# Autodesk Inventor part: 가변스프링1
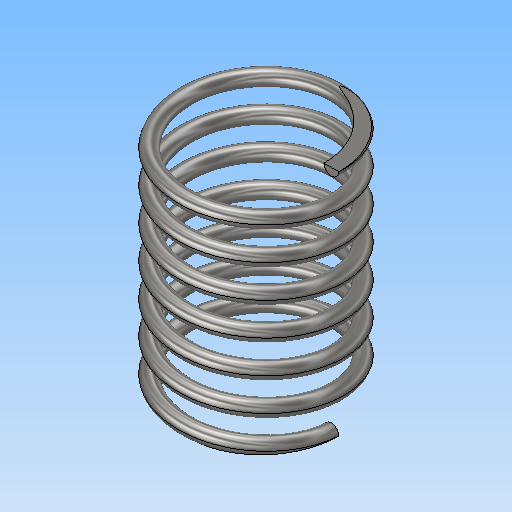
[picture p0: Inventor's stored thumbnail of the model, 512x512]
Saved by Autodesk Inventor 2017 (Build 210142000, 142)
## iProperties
Part Number: 가변스프링1
Material: 스테인레스 스틸
Document SubType Name: Modeling
Designer: MRC
Density: 8 g/cm^3
Appearance: 반연마
Mass: 10.9602 g
Surface Area: 27.6886 cm^2
Volume: 1.37003 cm^3
Author: MRC
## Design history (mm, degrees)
sketch "스케치1"
  geometry: L1 (0, 0)-(10, 0); L2 (10, 0)-(10, 30.358); L3 (10, 30.358)-(0, 30.358); L4 (0, 30.358)-(0, 0); C1 r 1 at (10, 0)
  constraints: 8 end point, 2 parallel, 1 centre point, 1 coincident, 1 horizontal, 1 perpendicular
  dimensions: "d1" = 30.35829 distance of L3.end L1.start (derived); "d2" = 20 diameter of L2 L4; "d3" = 2 diameter of C1
feature "코일1" sketch "스케치1" pitch "d4" = 10; turns "d6" = 7; dims "d5" = 30.35829 (= d1), "d7" = 0, angle "d8" = 90 deg, angle "d9" = 90 deg, "d10" = 0, "d11" = 0
sketch "스케치2"
  geometry: L1 (-20, 30.358)-(20, 30.358); L2 (20, 30.358)-(20, 0); L3 (20, 0)-(-20, 0); L4 (-20, 0)-(-20, 30.358); L5 (0, 30.358)-(0, 0) reference; 2 further points
  constraints: 8 end point, 2 midpoint, 2 parallel, 1 coincident, 1 horizontal, 1 perpendicular
  dimensions: "d12" = 40 distance between parallel lines of L4 L2
extrude "돌출1" sketch "스케치2" stored distance "d13" = 0; taper "d14" = 0 deg
node "솔리드1"
